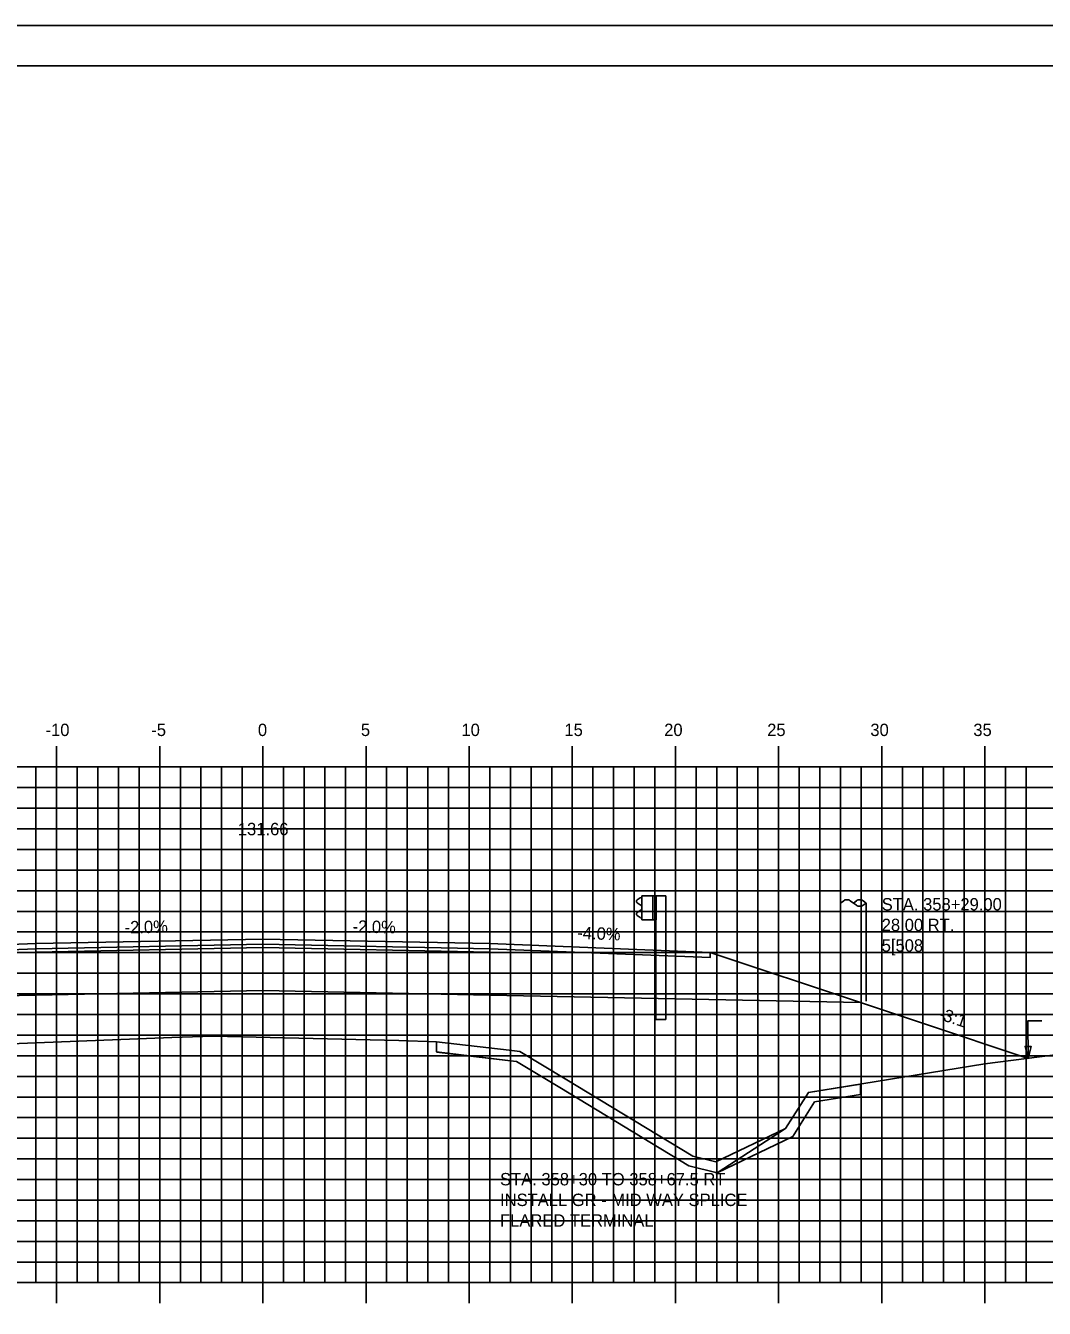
# Model space of a CAD drawing. Extents: x 1146081 to 1146251, y 608981 to 609091.
# Drawn here: x 1146152.7 to 1146202, y 609029.1 to 609091.3 of the extents above; entities that cross this region are included whole.
import ezdxf

# ---------------------------------------------------------------- set-up
doc = ezdxf.new("R2010")
doc.units = 0
for name, color, linetype in [('ANNOTATION', 7, 'Continuous'), ('BORDER', 7, 'Continuous'), ('D_Guardrail_Beam_Rt', 7, 'Continuous'), ('D_Guardrail_ConcBarrier', 7, 'Continuous'), ('D_Roadway_Centerline', 7, 'Continuous'), ('D_Roadway_Centerline_Text', 7, 'Continuous'), ('D_Roadway_Edge_Shoulder', 7, 'Continuous'), ('D_Roadway_Edge_TW', 7, 'Continuous'), ('D_Roadway_Pavement', 7, 'Continuous'), ('D_Roadway_SlopeLines', 7, 'Continuous'), ('D_Roadway_SubGrade', 7, 'Continuous'), ('D_Text_Standard', 7, 'Continuous'), ('D_Utilities_Pole_Joint_Rt', 7, 'Continuous'), ('H_V ANNOTATION', 7, 'Continuous'), ('MAJOR', 7, 'Continuous'), ('MINOR', 7, 'Continuous'), ('PLOT BOUNDARY', 7, 'Continuous'), ('S_Roadway_Centerline', 7, 'Continuous'), ('SHADING', 7, 'Continuous')]:
    doc.layers.add(name, color=color, linetype=linetype)

msp = doc.modelspace()

# ---------------------------------------------------------------- linework, layer by layer
msp.add_lwpolyline([(1146120.332, 609036.972), (1146136.678, 609043), (1146139.39, 609044), (1146146.157, 609046.495), (1146146.158, 609046.495), (1146153.158, 609046.775), (1146164.158, 609046.995), (1146175.158, 609046.775), (1146185.834, 609046.348), (1146193.131, 609043.915), (1146196.131, 609042.915), (1146201.256, 609041.207)])
at = {"layer": 'BORDER'}
msp.add_lwpolyline([(1146089.158, 608984.335), (1146249.158, 608984.335), (1146249.158, 609089.335), (1146089.158, 609089.335)], close=True, dxfattribs=at)
at = {"layer": 'D_Guardrail_Beam_Rt'}
for p, q in [((1146182.446, 609048.992), (1146182.302, 609048.892)), ((1146182.536, 609049.013), (1146182.462, 609048.998)), ((1146182.302, 609048.749), (1146182.498, 609048.613)), ((1146182.498, 609048.414), (1146182.302, 609048.277)), ((1146182.531, 609048.548), (1146182.531, 609048.478)), ((1146182.302, 609048.134), (1146182.446, 609048.034)), ((1146182.462, 609048.028), (1146182.536, 609048.013))]:
    msp.add_line(p, q, dxfattribs=at)
for centre, major_axis, start_param, end_param in [((1146182.47, 609048.958), (-0.0417, 0), 4.907132, 5.323254), ((1146182.353, 609048.82), (-0.0877, 0), 5.323254, 7.243116), ((1146182.452, 609048.548), (0.0789, 0), 0, 0.959931), ((1146182.452, 609048.478), (0.0789, 0), 5.323254, 6.283185), ((1146182.353, 609048.206), (-0.0877, 0), 5.323254, 7.243116), ((1146182.47, 609048.068), (-0.0417, 0), 0.959931, 1.376053)]:
    msp.add_ellipse(centre, major_axis=major_axis, ratio=0.995501, start_param=start_param, end_param=end_param, dxfattribs=at)
at = {"layer": 'D_Guardrail_ConcBarrier'}
for p, q in [((1146182.536, 609049.096), (1146183.223, 609049.096)), ((1146182.536, 609047.93), (1146182.536, 609049.096)), ((1146183.057, 609049.096), (1146183.057, 609047.93)), ((1146183.161, 609049.096), (1146183.161, 609047.93)), ((1146183.223, 609049.096), (1146183.694, 609049.096)), ((1146183.223, 609049.096), (1146183.223, 609047.93)), ((1146183.694, 609049.096), (1146183.694, 609043.096)), ((1146183.223, 609047.93), (1146182.536, 609047.93)), ((1146183.202, 609043.096), (1146183.202, 609047.93)), ((1146183.202, 609043.096), (1146183.694, 609043.096))]:
    msp.add_line(p, q, dxfattribs=at)
at = {"layer": 'D_Roadway_Edge_Shoulder'}
for points in [[(1146153.158, 609046.775), (1146146.158, 609046.495), (1146146.158, 609046.245), (1146153.158, 609046.525)], [(1146175.158, 609046.775), (1146185.834, 609046.348), (1146185.834, 609046.098), (1146175.158, 609046.525)]]:
    msp.add_lwpolyline(points, close=True, dxfattribs=at)
at = {"layer": 'D_Roadway_Edge_TW'}
msp.add_lwpolyline([(1146153.158, 609046.525), (1146153.158, 609046.775), (1146164.158, 609046.995), (1146175.158, 609046.775), (1146175.158, 609046.525), (1146164.158, 609046.745)], close=True, dxfattribs=at)
at = {"layer": 'D_Roadway_Pavement'}
msp.add_lwpolyline([(1146153.158, 609046.358), (1146153.158, 609046.525), (1146164.158, 609046.745), (1146175.158, 609046.525), (1146175.158, 609046.358), (1146164.158, 609046.578)], close=True, dxfattribs=at)
at = {"layer": 'D_Roadway_SlopeLines'}
for points in [[(1146193.131, 609043.915), (1146196.131, 609042.915)], [(1146196.131, 609042.915), (1146201.256, 609041.207)]]:
    msp.add_lwpolyline(points, dxfattribs=at)
at = {"layer": 'D_Roadway_SubGrade'}
for p, q in [((1146172.573, 609042.017), (1146172.573, 609041.517)), ((1146193.131, 609039.964), (1146193.131, 609039.459))]:
    msp.add_line(p, q, dxfattribs=at)
for points in [[(1146153.158, 609046.358), (1146153.158, 609046.525), (1146146.158, 609046.245), (1146146.158, 609046.495), (1146146.157, 609046.495), (1146139.39, 609044), (1146153.158, 609044.275)], [(1146153.158, 609044.275), (1146153.158, 609046.358), (1146164.158, 609046.578), (1146175.158, 609046.358), (1146175.158, 609044.275), (1146164.158, 609044.495)], [(1146175.158, 609046.358), (1146175.158, 609046.525), (1146185.834, 609046.098), (1146185.834, 609046.348), (1146185.834, 609046.348), (1146193.131, 609043.915), (1146175.158, 609044.275)]]:
    msp.add_lwpolyline(points, close=True, dxfattribs=at)
msp.add_lwpolyline([(1146172.573, 609041.514), (1146176.037, 609041.109), (1146176.453, 609041.054), (1146178.559, 609039.792), (1146184.801, 609035.995), (1146186.173, 609035.664), (1146189.843, 609037.427), (1146190.902, 609039.099), (1146193.131, 609039.459)], dxfattribs=at)
at = {"layer": 'D_Text_Standard'}
msp.add_lwpolyline([(1146201.256, 609041.207), (1146201.245, 609043.035), (1146201.925, 609043.035)], dxfattribs=at)
msp.add_lwpolyline([(1146201.256, 609041.207), (1146201.107, 609041.788), (1146201.398, 609041.79)], close=True, dxfattribs=at)
at = {"layer": 'D_Utilities_Pole_Joint_Rt'}
for p, q in [((1146192.158, 609048.739), (1146192.314, 609048.849)), ((1146192.158, 609043.981), (1146192.158, 609048.739)), ((1146192.627, 609048.849), (1146192.783, 609048.739)), ((1146192.939, 609048.849), (1146192.783, 609048.739)), ((1146192.783, 609048.739), (1146192.939, 609048.628)), ((1146193.408, 609048.739), (1146193.252, 609048.849)), ((1146193.252, 609048.628), (1146193.408, 609048.739)), ((1146193.408, 609043.981), (1146193.408, 609048.739))]:
    msp.add_line(p, q, dxfattribs=at)
for centre, start, end in [((1146192.471, 609048.629), 90, 125.26439), ((1146192.471, 609048.629), 54.73561, 90), ((1146193.096, 609048.629), 90, 125.26439), ((1146193.096, 609048.85), 234.73561, 270), ((1146193.096, 609048.629), 54.73561, 90), ((1146193.096, 609048.85), 270, 305.26439)]:
    msp.add_arc(centre, 0.271, start, end, dxfattribs=at)
at = {"layer": 'MAJOR'}
for p, q in [((1146154.158, 609056.337), (1146154.158, 609055.335)), ((1146159.158, 609056.337), (1146159.158, 609055.335)), ((1146164.158, 609056.337), (1146164.158, 609055.335)), ((1146169.158, 609056.337), (1146169.158, 609055.335)), ((1146174.158, 609056.337), (1146174.158, 609055.335)), ((1146179.158, 609056.337), (1146179.158, 609055.335)), ((1146184.158, 609056.337), (1146184.158, 609055.335)), ((1146189.158, 609056.337), (1146189.158, 609055.335)), ((1146194.158, 609056.337), (1146194.158, 609055.335)), ((1146199.158, 609056.337), (1146199.158, 609055.335)), ((1146094.158, 609055.335), (1146234.158, 609055.335)), ((1146094.158, 609055.335), (1146234.158, 609055.335)), ((1146154.158, 609030.335), (1146154.158, 609055.335)), ((1146159.158, 609030.335), (1146159.158, 609055.335)), ((1146164.158, 609030.335), (1146164.158, 609055.335)), ((1146169.158, 609030.335), (1146169.158, 609055.335)), ((1146174.158, 609030.335), (1146174.158, 609055.335)), ((1146179.158, 609030.335), (1146179.158, 609055.335)), ((1146184.158, 609030.335), (1146184.158, 609055.335)), ((1146189.158, 609030.335), (1146189.158, 609055.335)), ((1146194.158, 609030.335), (1146194.158, 609055.335)), ((1146199.158, 609030.335), (1146199.158, 609055.335)), ((1146094.158, 609050.335), (1146234.158, 609050.335)), ((1146094.158, 609045.335), (1146234.158, 609045.335)), ((1146094.158, 609040.335), (1146234.158, 609040.335)), ((1146094.158, 609035.335), (1146234.158, 609035.335)), ((1146094.158, 609030.335), (1146234.158, 609030.335)), ((1146094.158, 609030.335), (1146234.158, 609030.335)), ((1146154.158, 609029.333), (1146154.158, 609030.335)), ((1146159.158, 609029.333), (1146159.158, 609030.335)), ((1146164.158, 609029.333), (1146164.158, 609030.335)), ((1146169.158, 609029.333), (1146169.158, 609030.335)), ((1146174.158, 609029.333), (1146174.158, 609030.335)), ((1146179.158, 609029.333), (1146179.158, 609030.335)), ((1146184.158, 609029.333), (1146184.158, 609030.335)), ((1146189.158, 609029.333), (1146189.158, 609030.335)), ((1146194.158, 609029.333), (1146194.158, 609030.335)), ((1146199.158, 609029.333), (1146199.158, 609030.335))]:
    msp.add_line(p, q, dxfattribs=at)
at = {"layer": 'MINOR'}
for p, q in [((1146153.158, 609030.335), (1146153.158, 609055.335)), ((1146155.158, 609030.335), (1146155.158, 609055.335)), ((1146156.158, 609030.335), (1146156.158, 609055.335)), ((1146157.158, 609030.335), (1146157.158, 609055.335)), ((1146158.158, 609030.335), (1146158.158, 609055.335)), ((1146160.158, 609030.335), (1146160.158, 609055.335)), ((1146161.158, 609030.335), (1146161.158, 609055.335)), ((1146162.158, 609030.335), (1146162.158, 609055.335)), ((1146163.158, 609030.335), (1146163.158, 609055.335)), ((1146165.158, 609030.335), (1146165.158, 609055.335)), ((1146166.158, 609030.335), (1146166.158, 609055.335)), ((1146167.158, 609030.335), (1146167.158, 609055.335)), ((1146168.158, 609030.335), (1146168.158, 609055.335)), ((1146170.158, 609030.335), (1146170.158, 609055.335)), ((1146171.158, 609030.335), (1146171.158, 609055.335)), ((1146172.158, 609030.335), (1146172.158, 609055.335)), ((1146173.158, 609030.335), (1146173.158, 609055.335)), ((1146175.158, 609030.335), (1146175.158, 609055.335)), ((1146176.158, 609030.335), (1146176.158, 609055.335)), ((1146177.158, 609030.335), (1146177.158, 609055.335)), ((1146178.158, 609030.335), (1146178.158, 609055.335)), ((1146180.158, 609030.335), (1146180.158, 609055.335)), ((1146181.158, 609030.335), (1146181.158, 609055.335)), ((1146182.158, 609030.335), (1146182.158, 609055.335)), ((1146183.158, 609030.335), (1146183.158, 609055.335)), ((1146185.158, 609030.335), (1146185.158, 609055.335)), ((1146186.158, 609030.335), (1146186.158, 609055.335)), ((1146187.158, 609030.335), (1146187.158, 609055.335)), ((1146188.158, 609030.335), (1146188.158, 609055.335)), ((1146190.158, 609030.335), (1146190.158, 609055.335)), ((1146191.158, 609030.335), (1146191.158, 609055.335)), ((1146192.158, 609030.335), (1146192.158, 609055.335)), ((1146193.158, 609030.335), (1146193.158, 609055.335)), ((1146195.158, 609030.335), (1146195.158, 609055.335)), ((1146196.158, 609030.335), (1146196.158, 609055.335)), ((1146197.158, 609030.335), (1146197.158, 609055.335)), ((1146198.158, 609030.335), (1146198.158, 609055.335)), ((1146200.158, 609030.335), (1146200.158, 609055.335)), ((1146201.158, 609030.335), (1146201.158, 609055.335)), ((1146094.158, 609054.335), (1146234.158, 609054.335)), ((1146094.158, 609053.335), (1146234.158, 609053.335)), ((1146094.158, 609052.335), (1146234.158, 609052.335)), ((1146094.158, 609051.335), (1146234.158, 609051.335)), ((1146094.158, 609049.335), (1146234.158, 609049.335)), ((1146094.158, 609048.335), (1146234.158, 609048.335)), ((1146094.158, 609047.335), (1146234.158, 609047.335)), ((1146094.158, 609046.335), (1146234.158, 609046.335)), ((1146094.158, 609044.335), (1146234.158, 609044.335)), ((1146094.158, 609043.335), (1146234.158, 609043.335)), ((1146094.158, 609042.335), (1146234.158, 609042.335)), ((1146094.158, 609041.335), (1146234.158, 609041.335)), ((1146094.158, 609039.335), (1146234.158, 609039.335)), ((1146094.158, 609038.335), (1146234.158, 609038.335)), ((1146094.158, 609037.335), (1146234.158, 609037.335)), ((1146094.158, 609036.335), (1146234.158, 609036.335)), ((1146094.158, 609034.335), (1146234.158, 609034.335)), ((1146094.158, 609033.335), (1146234.158, 609033.335)), ((1146094.158, 609032.335), (1146234.158, 609032.335)), ((1146094.158, 609031.335), (1146234.158, 609031.335))]:
    msp.add_line(p, q, dxfattribs=at)
at = {"layer": 'PLOT BOUNDARY'}
msp.add_lwpolyline([(1146081.065, 608981.276), (1146251.065, 608981.276), (1146251.065, 609091.276), (1146081.065, 609091.276)], close=True, dxfattribs=at)
at = {"layer": 'S_Roadway_Centerline'}
msp.add_lwpolyline([(1146109.994, 609036.218), (1146127.386, 609037.487), (1146129.573, 609037.653), (1146130.865, 609037.83), (1146136.476, 609038.551), (1146145.16, 609040.869), (1146146.117, 609041.121), (1146149.881, 609041.769), (1146150.681, 609041.862), (1146159.752, 609042.222), (1146161.743, 609042.288), (1146170.756, 609042.071), (1146172.573, 609042.017), (1146176.099, 609041.605), (1146176.621, 609041.535), (1146178.817, 609040.219), (1146184.994, 609036.462), (1146186.117, 609036.191), (1146189.498, 609037.815), (1146190.601, 609039.556), (1146199.152, 609040.937), (1146222.375, 609043.92)], dxfattribs=at)
at = {"layer": 'SHADING'}
msp.add_line((1146172.573, 609042.017), (1146172.573, 609041.517), dxfattribs=at)
for points in [[(1146189.498, 609037.815), (1146186.117, 609036.191), (1146184.994, 609036.462), (1146178.817, 609040.219), (1146176.621, 609041.535), (1146176.099, 609041.605), (1146172.573, 609042.017)], [(1146172.573, 609041.517), (1146176.037, 609041.109), (1146176.453, 609041.054), (1146178.559, 609039.792), (1146184.801, 609035.995), (1146186.173, 609035.664), (1146189.498, 609037.815)]]:
    msp.add_lwpolyline(points, dxfattribs=at)
msp.add_lwpolyline([(1146186.173, 609035.664), (1146189.843, 609037.427), (1146190.902, 609039.099), (1146193.131, 609039.459), (1146193.131, 609039.964), (1146190.601, 609039.556), (1146189.498, 609037.815)], close=True, dxfattribs=at)

# ---------------------------------------------------------------- texts
at = {"layer": 'ANNOTATION'}
for s, rotation, p in [('-2.0%', 1.14576, (1146157.461, 609047.261)), ('-2.0%', 358.85424, (1146168.501, 609047.308)), ('-4.0%', 357.70939, (1146179.392, 609047.006)), ('-3:1', 341.56505, (1146196.843, 609043.132))]:
    msp.add_text(s, height=0.6, rotation=rotation, dxfattribs=at).set_placement(p)
for s, p in [('STA. 358+30 TO 358+67.5 RT', (1146175.655, 609035.051)), ('INSTALL GR - MID WAY SPLICE', (1146175.655, 609034.049)), ('FLARED TERMINAL', (1146175.655, 609033.047))]:
    msp.add_text(s, height=0.6, dxfattribs=at).set_placement(p)
at = {"layer": 'D_Roadway_Centerline'}
for s, p in [('C', (1146164.153, 609046.995)), ('L', (1146164.158, 609046.988))]:
    msp.add_text(s, height=0.0146, dxfattribs=at).set_placement(p)
at = {"layer": 'D_Roadway_Centerline_Text'}
msp.add_text('131.66', height=0.6, dxfattribs=at).set_placement((1146162.944, 609052.027))
at = {"layer": 'D_Text_Standard'}
for s, p in [('STA. 358+29.00', (1146194.158, 609048.379)), ('28.00 RT.', (1146194.158, 609047.377)), ('5[508 ', (1146194.158, 609046.381))]:
    msp.add_text(s, height=0.6, dxfattribs=at).set_placement(p)
at = {"layer": 'H_V ANNOTATION'}
for s, p in [('-10', (1146153.623, 609056.835)), ('-5', (1146158.749, 609056.835)), ('0', (1146163.917, 609056.835)), ('5', (1146168.909, 609056.835)), ('10', (1146173.784, 609056.835)), ('15', (1146178.776, 609056.835)), ('20', (1146183.612, 609056.835)), ('25', (1146188.604, 609056.835)), ('30', (1146193.607, 609056.835)), ('35', (1146198.599, 609056.835))]:
    msp.add_text(s, height=0.6, dxfattribs=at).set_placement(p)
at = {"layer": 'S_Roadway_Centerline'}
for s, p in [('L', (1146161.734, 609042.281)), ('C', (1146161.737, 609042.288))]:
    msp.add_text(s, height=0.0146, dxfattribs=at).set_placement(p)

doc.saveas('drawing.dxf')
